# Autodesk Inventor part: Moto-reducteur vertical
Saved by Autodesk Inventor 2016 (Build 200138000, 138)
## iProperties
Created: 2013-08
Part Number: Moto-reducteur vertical
Material: Générique
Document SubType Name: Modeling
Designer: hilarion
Density: 1 g/cm^3
Appearance: Par défaut
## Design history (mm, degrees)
node "Moto-reducteur vertical1"
node "Moto-reducteur vertical"
node "Base1"
